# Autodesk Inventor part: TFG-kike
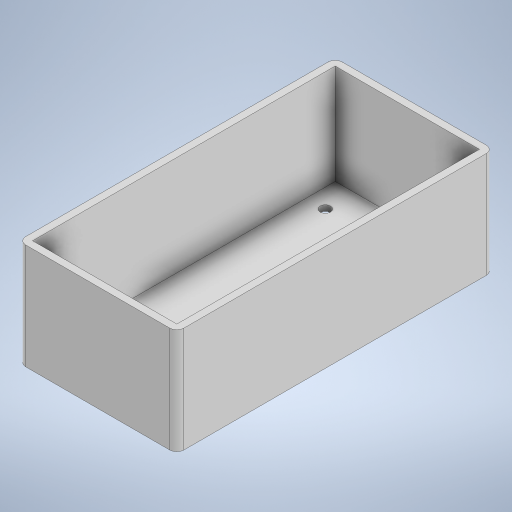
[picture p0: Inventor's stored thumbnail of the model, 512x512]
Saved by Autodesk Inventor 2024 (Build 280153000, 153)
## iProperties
Created: 2023-05
Part Number: TFG-kike
Material: Generic
Document SubType Name: Modeling
Designer: luisi
Density: 1 g/cm^3
Appearance: Default
Author: luisi
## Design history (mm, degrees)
sketch "Sketch1"
  geometry: 1 further point
sketch "Sketch2"
  geometry: L1 (-22.5, 45)-(22.5, 45); L2 (22.5, 45)-(22.5, -45); L3 (22.5, -45)-(-22.5, -45); L4 (-22.5, -45)-(-22.5, 45); L5 (-22.5, 45)-(22.5, -45); L6 (22.5, 45)-(-22.5, -45); 1 further point
  constraints: 12 end point, 2 midpoint, 2 parallel, 1 horizontal, 1 perpendicular
  dimensions: "d0" = 45 distance of L2.end L3.end; "d1" = 90 distance of L1.end L2.end
extrude "Extrusion1" new body sketch "Sketch2" distance "d2" = 30; taper "d3" = 0 deg
sketch "Sketch3"
  geometry: L1 (20.5, -43)-(-20.5, -43); L2 (-20.5, -43)-(-20.5, 43); L3 (-20.5, 43)-(20.5, 43); L4 (20.5, 43)-(20.5, -43); L5 (20.5, -43)-(-20.5, 43); L6 (-20.5, -43)-(20.5, 43); L7 (22.5, 45)-(-22.5, 45) reference; L8 (-22.5, -45)-(22.5, -45) reference; L9 (-22.5, 45)-(-22.5, -45) reference; 1 further point
  constraints: 12 end point, 2 midpoint, 2 parallel, 1 horizontal, 1 perpendicular
  dimensions: "d4" = 2 distance between parallel lines of L3 L7; "d5" = 2 distance between parallel lines of L8 L1 (derived); "d6" = 2 distance between parallel lines of L9 L2
extrude "Extrusion2" cut sketch "Sketch3" distance "d7" = 28.4125; taper "d8" = 0 deg
sketch "Sketch4"
  geometry: C1 r 1.5 at (12.841, 34.803); C2 r 1.5 at (-15.099, 34.803); C3 r 1.5 at (17.132, -15.997); 1 further point
  constraints: 3 centre point
  dimensions: "d9" = 3 diameter of C1; "d10" = 3 diameter of C2; "d11" = 3 diameter of C3; "d12" = 27.94 distance of C2.centre C1.centre; "d13" = 50.8 vertical distance of C3.centre C1.centre
extrude "Extrusion3" cut sketch "Sketch4" extent not by distance; stored distance "d14" = 0; taper "d15" = 0 deg
fillet "Fillet1" dims "d16" = 2
body "Solid1"
